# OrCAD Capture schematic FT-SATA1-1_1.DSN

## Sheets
1 INDEX: title: 01-INDEX; rev: 1.1
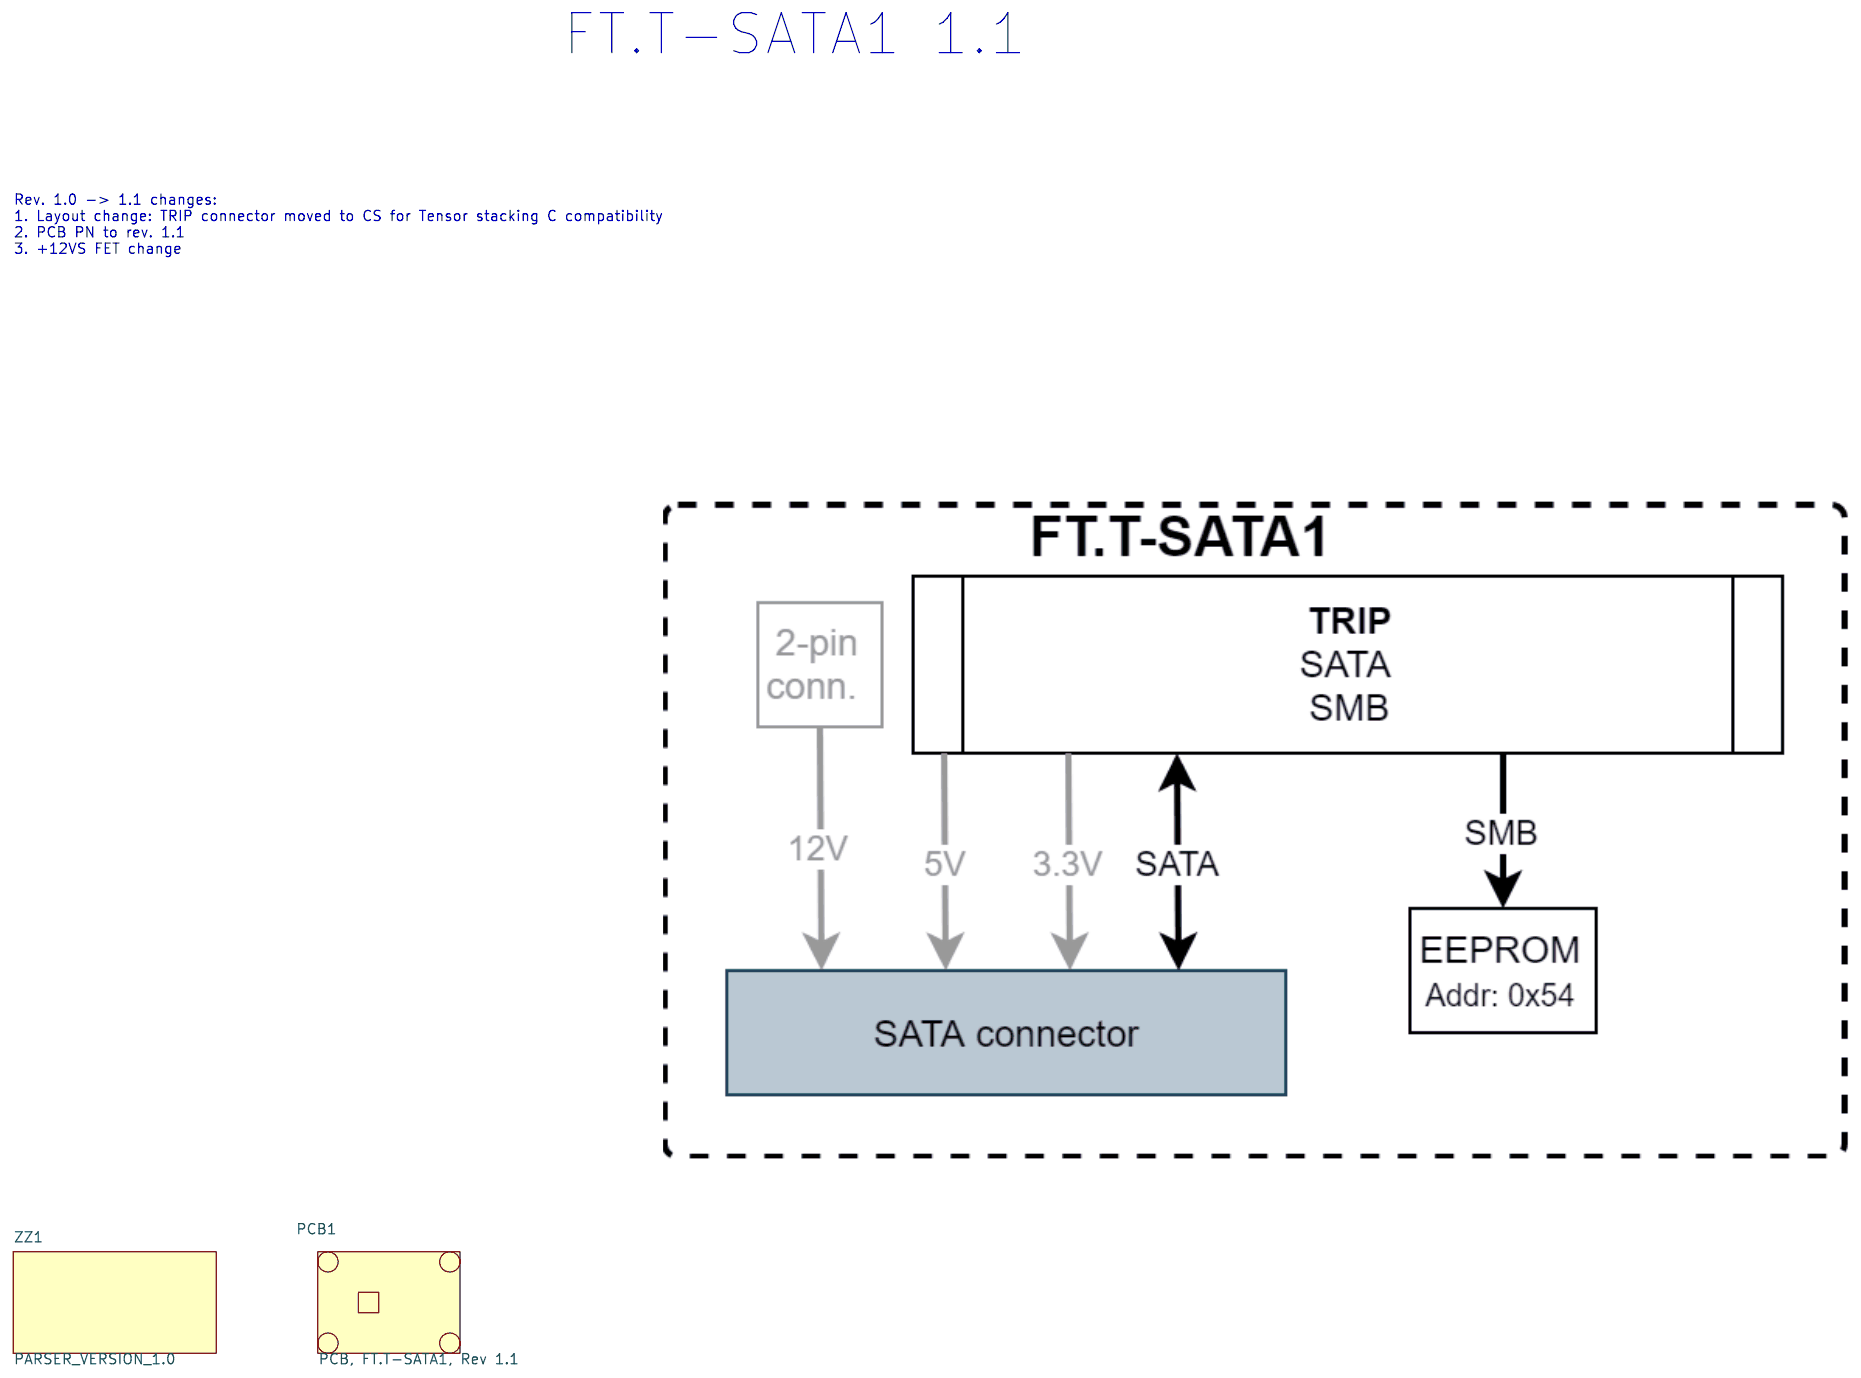
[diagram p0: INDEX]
2 TRIP: size A; title: 02-TRIP
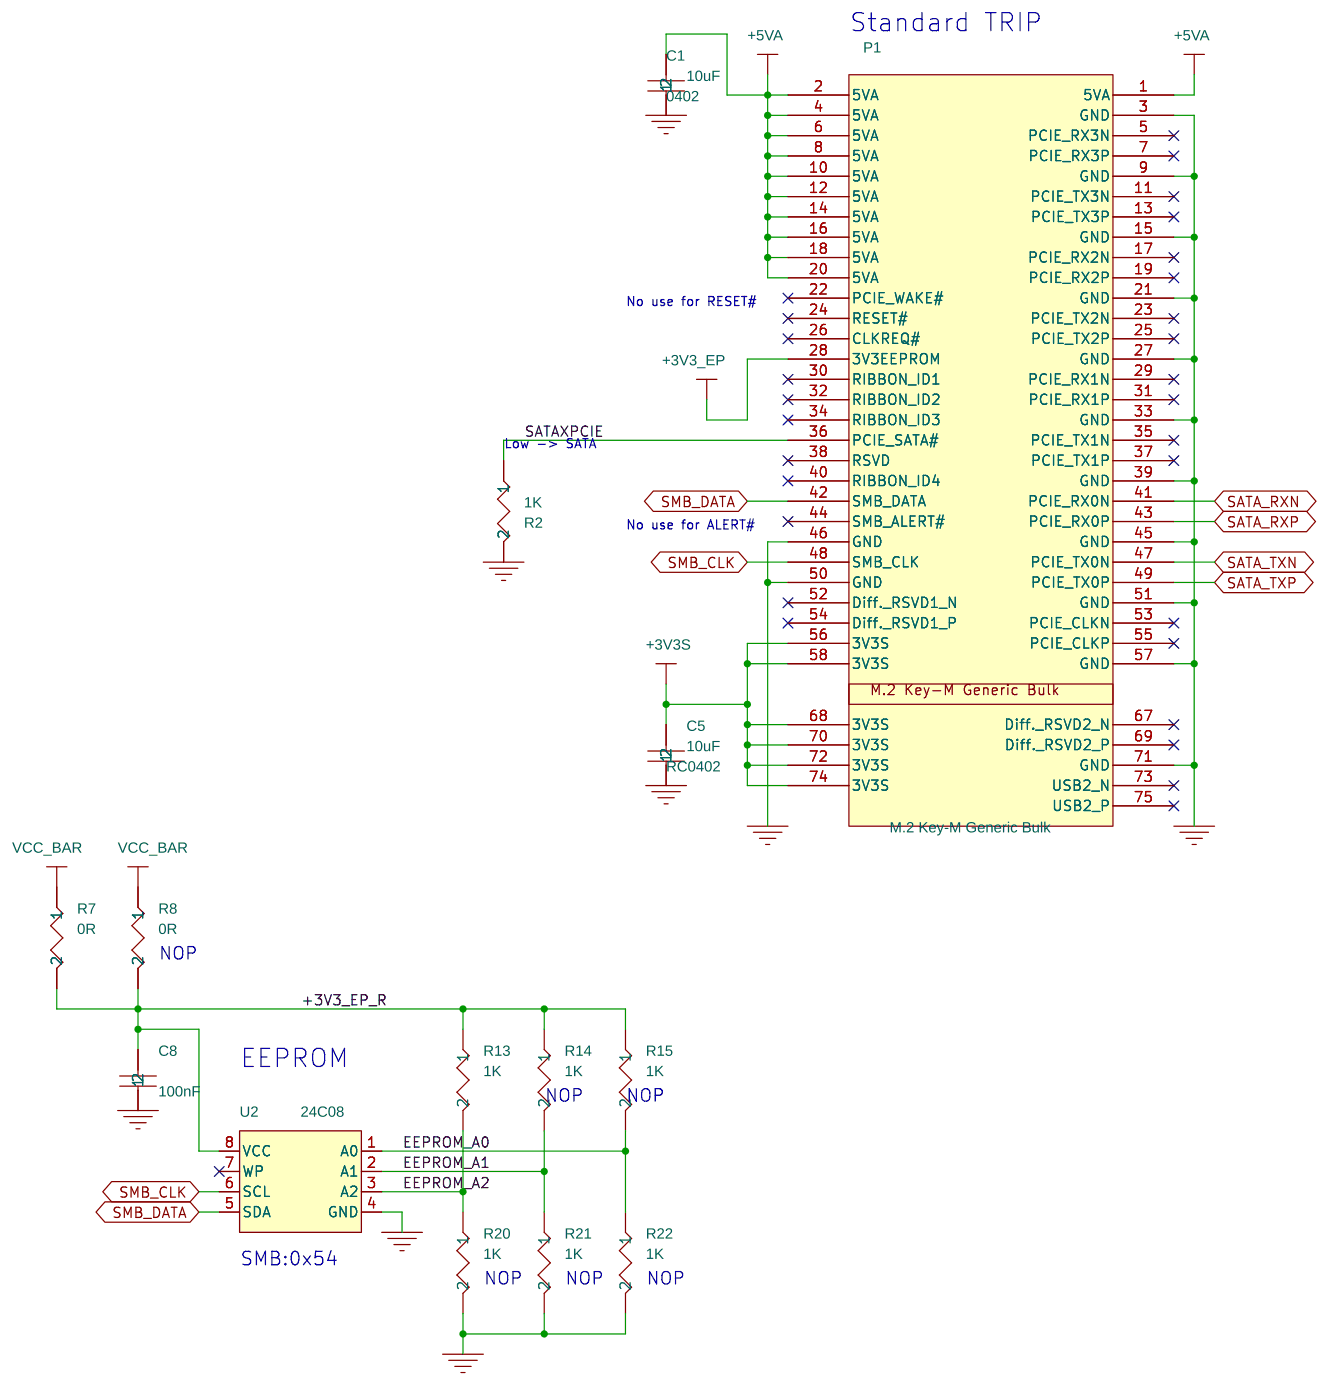
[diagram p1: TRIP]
3 SATA: size A4; title: 03-SATA
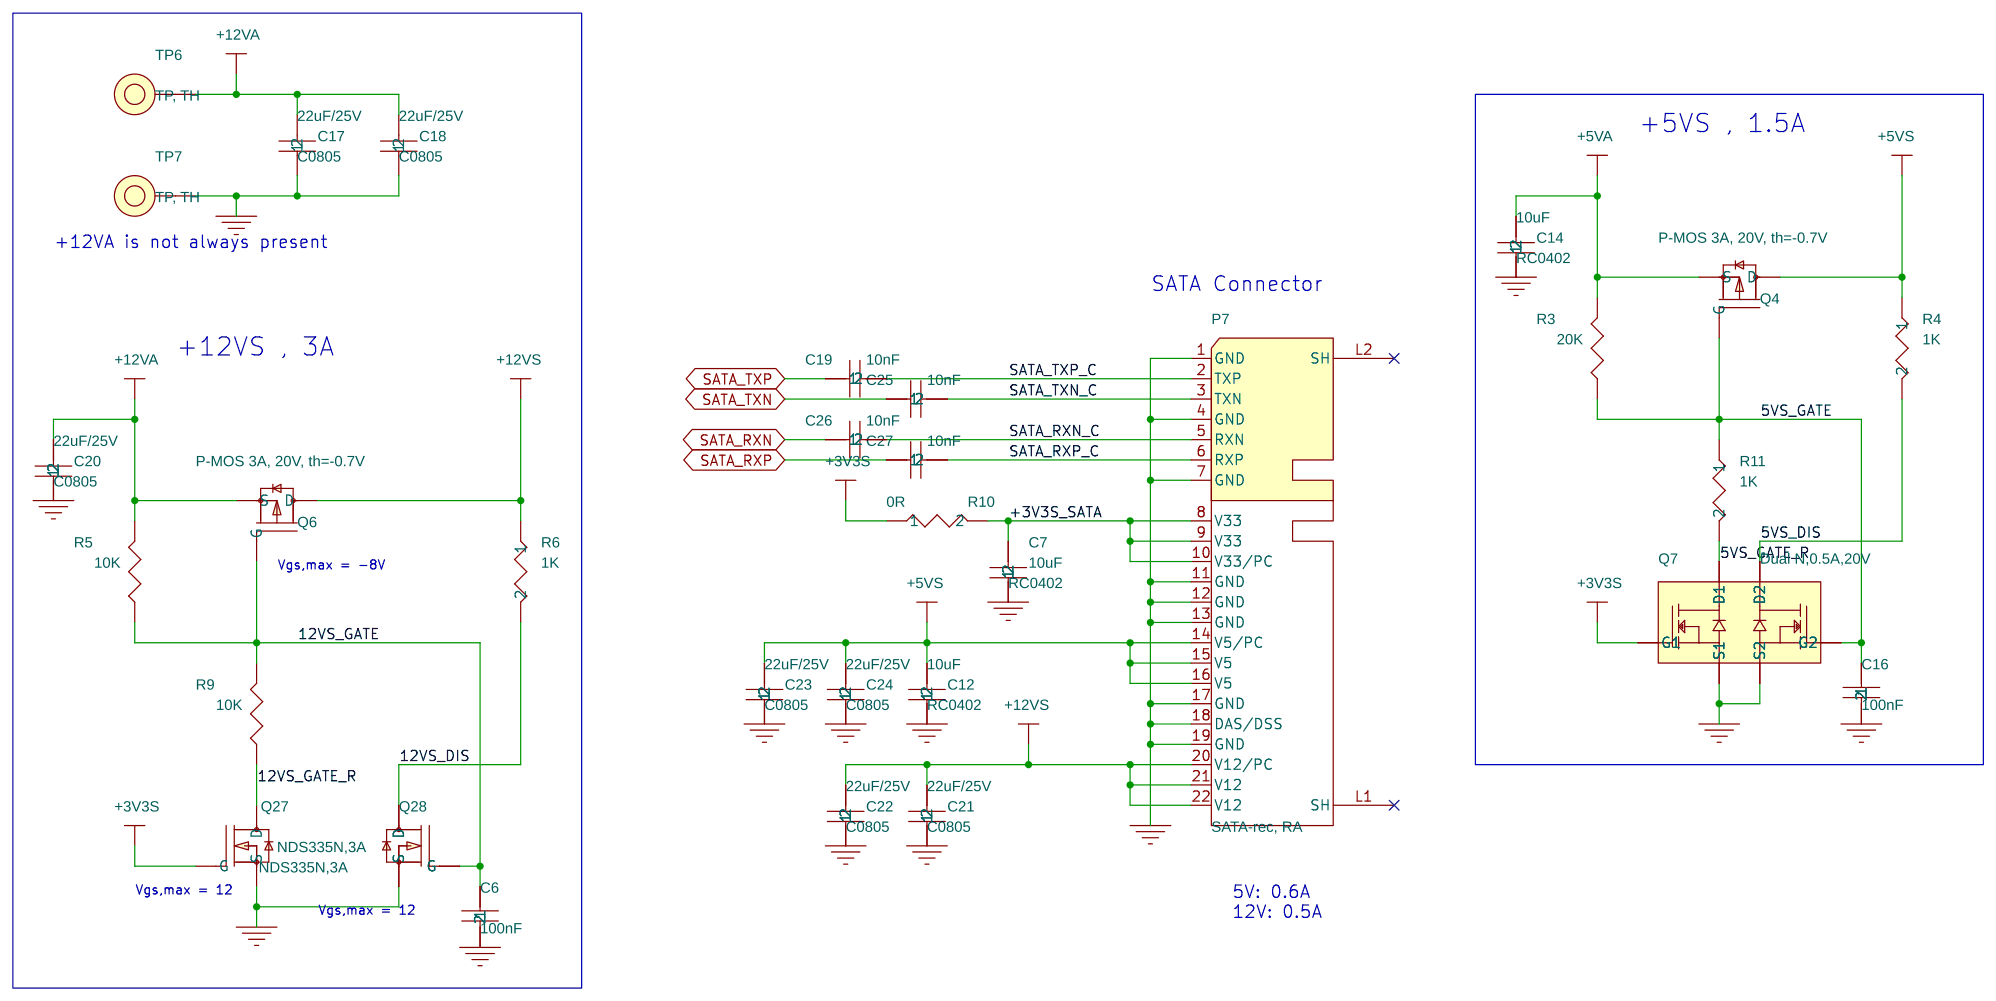
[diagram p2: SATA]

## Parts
sheet INDEX
PCB1  PCB, FT.T-SATA1, Rev 1.1
ZZ1  PARSER_VERSION_1.0
sheet SATA
C6  100nF  [RC0402]
C7  10uF  [RC0402]
C12  10uF  [RC0402]
C14  10uF  [RC0402]
C16  100nF  [RC0402]
C17  22uF/25V  [C0805]
C18  22uF/25V  [C0805]
C19  10nF  [RC0402]
C20  22uF/25V  [C0805]
C21  22uF/25V  [C0805]
C22  22uF/25V  [C0805]
C23  22uF/25V  [C0805]
C24  22uF/25V  [C0805]
C25  10nF  [RC0402]
C26  10nF  [RC0402]
C27  10nF  [RC0402]
P7  SATA-rec, RA  [SATA-22-V-TH]
Q4  P-MOS 3A, 20V, th=-0.7V  [SOT23]
Q6  P-MOS 3A, 20V, th=-0.7V  [SOT23]
Q7  Dual N,0.5A,20V  [SOT-563-6]
Q27  NDS335N,3A  [SOT23]
Q28  NDS335N,3A  [SOT23]
R3  20K  [RC0402]
R4  1K  [RC0402]
R5  10K  [RC0402]
R6  1K  [RC0402]
R9  10K  [RC0402]
R10  0R  [RC0402]
R11  1K  [RC0402]
TP6  TP, TH  [TPRTH2m]
TP7  TP, TH  [TPRTH2m]
sheet TRIP
C1  10uF  [0402]
C5  10uF  [RC0402]
C8  100nF  [RC0402]
P1  M.2 Key-M Generic Bulk  [NGFF67P8HMkeySM]
R2  1K  [RC0402]
R7  0R  [RC0402]
R8  0R  [RC0402]
R13  1K  [RC0402]
R14  1K  [RC0402]
R15  1K  [RC0402]
R20  1K  [RC0402]
R21  1K  [RC0402]
R22  1K  [RC0402]
U2  24C08  [MO-229VCED-2]

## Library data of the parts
PCB1 = SBC-iHSW_Rev_1.0: CLABCONF0: FT.T-SATA1; P/N: 188C03561U
ZZ1 = PARSER_VERSION_1.0: CLABCONF0: FT.T-SATA1
C6 = 100nF,_10V,_X7R,_10%,_0402_3: CLABCONF0: FT.T-SATA1; P/N: 151C10400S
C7 = 100nF,_10V,_X7R,_10%,_0402_8: CLABCONF0: FT.T-SATA1; P/N: 151B10600S
C12 = 100nF,_10V,_X7R,_10%,_0402_10: CLABCONF0: FT.T-SATA1; P/N: 151B10600S
C14 = 100nF,_10V,_X7R,_10%,_0402_7: CLABCONF0: FT.T-SATA1; P/N: 151B10600S
C16 = 100nF,_10V,_X7R,_10%,_0402_4: CLABCONF0: FT.T-SATA1; P/N: 151C10400S
C17 = 100nF,_10V,_X7R,_10%,_0402_11: CLABCONF0: FT.T-SATA1; P/N: 151C22620S
C18 = 100nF,_10V,_X7R,_10%,_0402_15: CLABCONF0: FT.T-SATA1; P/N: 151C22620S
C19 = 100nF,_10V,_X7R,_10%,_0402_12: CLABCONF0: FT.T-SATA1; P/N: 151C10300S
C20 = 100nF,_10V,_X7R,_10%,_0402_9: CLABCONF0: FT.T-SATA1; P/N: 151C22620S
C21 = 100nF,_10V,_X7R,_10%,_0402_14: CLABCONF0: FT.T-SATA1; P/N: 151C22620S
C22 = 100nF,_10V,_X7R,_10%,_0402_5: CLABCONF0: FT.T-SATA1; P/N: 151C22620S
C23 = 100nF,_10V,_X7R,_10%,_0402_13: CLABCONF0: FT.T-SATA1; P/N: 151C22620S
C24 = 100nF,_10V,_X7R,_10%,_0402: CLABCONF0: FT.T-SATA1; P/N: 151C22620S
C25 = 100nF,_10V,_X7R,_10%,_0402_6: CLABCONF0: FT.T-SATA1; P/N: 151C10300S
C26 = 100nF,_10V,_X7R,_10%,_0402_2: CLABCONF0: FT.T-SATA1; P/N: 151C10300S
C27 = 100nF,_10V,_X7R,_10%,_0402_1: CLABCONF0: FT.T-SATA1; P/N: 151C10300S
P7 = Conn.,_SATA_-_Rec,_15+7,_Vert: CLABCONF0: FT.T-SATA1; P/N: 180K02201S
Q4 Q6 = P-MOSFET,3A,20V,110mOhm@-1.8V: CLABCONF0: FT.T-SATA1; P/N: 131D41510S
Q7 = DUAL_N-MOSFET,_0.5A_20V: CLABCONF0: FT.T-SATA1
Q27 Q28 = N-MOSFET,NDS335N,100mOhm@2.5V: CLABCONF0: FT.T-SATA1
R3 = RESISTOR: CLABCONF0: FT.T-SATA1; P/N: 161C20021S
R4 = 348R,1%,0402,1_16W_1: CLABCONF0: FT.T-SATA1; P/N: 161C10011S
R5 R9 = RESISTOR: CLABCONF0: FT.T-SATA1; P/N: 161C10021S
R6 = 348R,1%,0402,1_16W_2: CLABCONF0: FT.T-SATA1; P/N: 161C10011S
R10 = 348R,1%,0402,1_16W: CLABCONF0: FT.T-SATA1; P/N: 161C00005S
R11 = 348R,1%,0402,1_16W_3: CLABCONF0: FT.T-SATA1; P/N: 161C10011S
TP6 TP7 = TestPoint_0: P/N: 188Z01380
C1 = 100nF,_10V,_X7R,_10%,_0402: CLABCONF0: FT.T-SATA1; P/N: 151B10600S
C5 = 100nF,_10V,_X7R,_10%,_0402_1: CLABCONF0: FT.T-SATA1; P/N: 151B10600S
C8 = 15pF,_50V,_NPO,_5%,_0402: CLABCONF0: FT.T-SATA1; P/N: 151C10400S
P1 = M.2_Key-M_Generic_Bulk: CLABCONF0: FT.T-SATA1; P/N: 182K06700S
R2 = 348R,1%,0402,1_16W_5: CLABCONF0: FT.T-SATA1; P/N: 161C10011S
R7 = 348R,1%,0402,1_16W_1: CLABCONF0: FT.T-SATA1; P/N: 161C00005S
R8 = 348R,1%,0402,1_16W: CLABCONF0: NOP; P/N: 161C00005S
R13 = 348R,1%,0402,1_16W_8: CLABCONF0: FT.T-SATA1; P/N: 161C10011S
R14 = 348R,1%,0402,1_16W_2: CLABCONF0: NOP; P/N: 161C10011S
R15 = 348R,1%,0402,1_16W_7: CLABCONF0: NOP; P/N: 161C10011S
R20 = 348R,1%,0402,1_16W_3: CLABCONF0: NOP; P/N: 161C10011S
R21 = 348R,1%,0402,1_16W_4: CLABCONF0: NOP; P/N: 161C10011S
R22 = 348R,1%,0402,1_16W_6: CLABCONF0: NOP; P/N: 161C10011S
U2 = 24C02,_serial_EE,_2KB,_I2C: CLABCONF0: FT.T-SATA1; P/N: 111S31000S

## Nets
5VS_DIS: Q7.3(D2) R4.2
5VS_GATE: C16.1 Q4.1(G) Q7.5(G2) R3.1 R11.1
5VS_GATE_R: Q7.6(D1) R11.2
12VS_DIS: Q28.3(D) R6.2
12VS_GATE: C6.1 Q6.1(G) Q28.1(G) R5.1 R9.2
12VS_GATE_R: Q27.3(D) R9.1
+3V3_EP: P1.28(3V3EEPROM) R7.1
+3V3_EP_R: C8.2 R7.2 R8.2 R13.1 R14.1 R15.1 U2.8(VCC)
+3V3S: C5.2 P1.56(3V3S) P1.58(3V3S) P1.68(3V3S) P1.70(3V3S) P1.72(3V3S) P1.74(3V3S) Q7.2(G1) Q27.1(G) R8.1 R10.1
+3V3S_SATA: C7.2 P7.8(V33) P7.9(V33) P7.10(V33/PC) R10.2
+5VA: C1.2 C14.2 P1.1(5VA) P1.2(5VA) P1.4(5VA) P1.6(5VA) P1.8(5VA) P1.10(5VA) P1.12(5VA) P1.14(5VA) P1.16(5VA) P1.18(5VA) P1.20(5VA) Q4.2(S) R3.2
+5VS: C12.2 C23.2 C24.2 P7.14(V5/PC) P7.15(V5) P7.16(V5) Q4.3(D) R4.1
+12VA: C17.2 C18.2 C20.2 Q6.2(S) R5.2 TP6.1
+12VS: C21.2 C22.2 P7.20(V12/PC) P7.21(V12) P7.22(V12) Q6.3(D) R6.1
GND: C1.1 C5.1 C6.2 C7.1 C8.1 C12.1 C14.1 C16.2 C17.1 C18.1 C20.1 C21.1 C22.1 C23.1 C24.1 P1.3(GND) P1.9(GND) P1.15(GND) P1.21(GND) P1.27(GND) P1.33(GND) P1.39(GND) P1.45(GND) P1.46(GND) P1.50(GND) P1.51(GND) P1.57(GND) P1.71(GND) P7.1(GND) P7.4(GND) P7.7(GND) P7.11(GND) P7.12(GND) P7.13(GND) P7.17(GND) P7.18(DAS/DSS) P7.19(GND) Q7.1(S1) Q7.4(S2) Q27.2(S) Q28.2(S) R2.2 R20.2 R21.2 R22.2 TP7.1 U2.4(GND)
EEPROM_A0: R15.2 R22.1 U2.1(A0)
EEPROM_A1: R14.2 R21.1 U2.2(A1)
EEPROM_A2: R13.2 R20.1 U2.3(A2)
SATA_RXN: C26.1 P1.41(PCIE_RX0N)
SATA_RXN_C: C26.2 P7.5(RXN)
SATA_RXP: C27.1 P1.43(PCIE_RX0P)
SATA_RXP_C: C27.2 P7.6(RXP)
SATA_TXN: C25.1 P1.47(PCIE_TX0N)
SATA_TXN_C: C25.2 P7.3(TXN)
SATA_TXP: C19.1 P1.49(PCIE_TX0P)
SATA_TXP_C: C19.2 P7.2(TXP)
SATAXPCIE: P1.36(PCIE_SATA#) R2.1
SMB_CLK: P1.48(SMB_CLK) U2.6(SCL)
SMB_DATA: P1.42(SMB_DATA) U2.5(SDA)

Not connected (* = marked no-connect by the designer): P1 5(PCIE_RX3N)* 7(PCIE_RX3P)* 11(PCIE_TX3N)* 13(PCIE_TX3P)* 17(PCIE_RX2N)* 19(PCIE_RX2P)* 22(PCIE_WAKE#)* 23(PCIE_TX2N)* 24(RESET#)* 25(PCIE_TX2P)* 26(CLKREQ#)* 29(PCIE_RX1N)* 30(RIBBON_ID1)* 31(PCIE_RX1P)* 32(RIBBON_ID2)* 34(RIBBON_ID3)* 35(PCIE_TX1N)* 37(PCIE_TX1P)* 38(RSVD)* 40(RIBBON_ID4)* 44(SMB_ALERT#)* 52(Diff._RSVD1_N)* 53(PCIE_CLKN)* 54(Diff._RSVD1_P)* 55(PCIE_CLKP)* 67(Diff._RSVD2_N)* 69(Diff._RSVD2_P)* 73(USB2_N)* 75(USB2_P)*; P7 L1(SH)* L2(SH)*; U2 7(WP)*

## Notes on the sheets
sheet 1
- FT.T-SATA1 1.1
- Rev. 1.0 -> 1.1 changes:
  1. Layout change: TRIP connector moved to CS for Tensor stacking C compatibility
  2. PCB PN to rev. 1.1
  3. +12VS FET change
sheet 2
- Standard TRIP
- No use for RESET#
- Low -> SATA
- No use for ALERT#
- NOP
- EEPROM
- NOP
- NOP
- SMB:0x54
- NOP
- NOP
- NOP
sheet 3
- +5VS , 1.5A
- +12VA is not always present
- SATA Connector
- +12VS , 3A
- Vgs,max = -8V
- Vgs,max = 12
- 5V: 0.6A
  12V: 0.5A
- Vgs,max = 12
